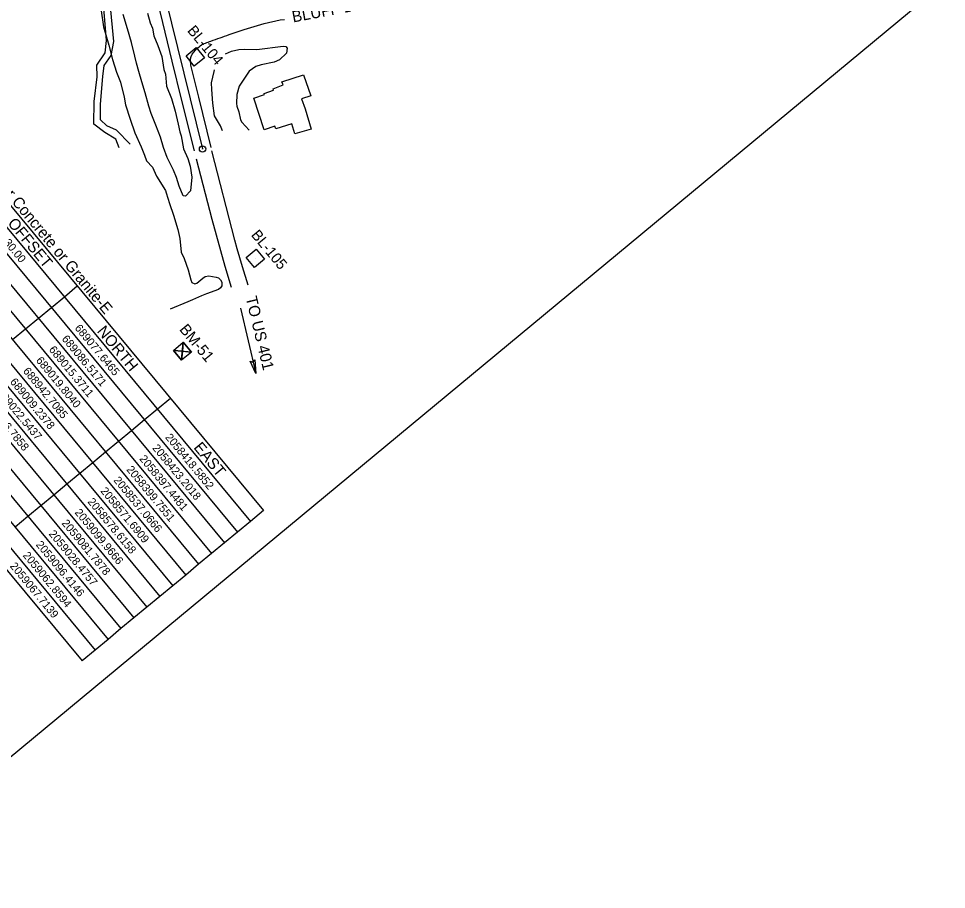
# Model space of a CAD drawing. Extents: x 2057130 to 2060012, y 687175 to 689912.
# Drawn here: x 2058941 to 2059967, y 687175 to 688138 of the extents above; entities that cross this region are included whole.
import ezdxf

# ---------------------------------------------------------------- set-up
doc = ezdxf.new("R2010")
doc.units = 0
for name, color, linetype in [('CTL Bench Mark CELL', 7, 'Continuous'), ('CTL Bench Mark Text', 7, 'Continuous'), ('CTL Sheet Border CELL', 7, 'Continuous'), ('CTL Sheet Notes CELL', 7, 'Continuous'), ('CTL Sheet Table Cell', 7, 'Continuous'), ('CTL Sheet Text', 7, 'Continuous'), ('CTL Supplemental Horizontal and Vertical CELL', 7, 'Continuous'), ('CTL Supplemental Horizontal and Vertical Text', 7, 'Continuous'), ('Default', 7, 'Continuous'), ('Exist Roads EOP', 7, 'Continuous'), ('Exist Roads Soil', 7, 'Continuous'), ('Old_Level_11', 7, 'Continuous'), ('Old_Level_3', 7, 'Continuous'), ('Old_Level_8', 7, 'Continuous'), ('Old_Level_9', 7, 'Continuous'), ('Prop Horizontal Alignment', 7, 'Continuous'), ('Prop Terminator CELL', 7, 'Continuous')]:
    doc.layers.add(name, color=color, linetype=linetype)

msp = doc.modelspace()

# ---------------------------------------------------------------- linework, layer by layer
at = {"layer": 'CTL Bench Mark CELL'}
msp.add_line((2059122.2, 687770), (2059122.2, 687770), dxfattribs=at)
msp.add_lwpolyline([(2059123.1, 687779.9), (2059132.1, 687769.1), (2059121.3, 687760.1), (2059112.3, 687770.9)], close=True, dxfattribs=at)
for points in [[(2059132.1, 687769.1), (2059112.3, 687770.9), (2059122.2, 687770), (2059121.3, 687760.1), (2059123.1, 687779.9)], [(2059122.2, 687770), (2059132.1, 687769.1), (2059123.1, 687779.9), (2059122.2, 687770)], [(2059122.2, 687770), (2059112.3, 687770.9), (2059121.3, 687760.1), (2059122.2, 687770)]]:
    msp.add_lwpolyline(points, dxfattribs=at)
at = {"layer": 'CTL Sheet Border CELL'}
msp.add_lwpolyline([(2059967.3, 688179.9), (2058531.1, 689911.9), (2057318.7, 688906.6), (2058754.9, 687174.6)], close=True, dxfattribs=at)
at = {"layer": 'CTL Sheet Table Cell'}
for p, q in [((2058768.5, 688128.2), (2059211.8, 687593.7)), ((2058754.2, 688116.4), (2059197.5, 687581.8)), ((2058739.9, 688104.5), (2059183.2, 687569.9)), ((2058725.6, 688092.6), (2059168.8, 687558)), ((2058711.2, 688080.7), (2059154.5, 687546.2)), ((2058696.9, 688068.9), (2059140.2, 687534.3)), ((2058682.6, 688057), (2059125.9, 687522.4)), ((2058668.3, 688045.1), (2059111.6, 687510.6)), ((2058654, 688033.2), (2059097.3, 687498.7)), ((2058639.6, 688021.4), (2059082.9, 687486.8)), ((2058625.3, 688009.5), (2059068.6, 687474.9)), ((2058611, 687997.6), (2059054.3, 687463.1)), ((2058596.7, 687985.7), (2059040, 687451.2)), ((2058582.4, 687973.9), (2059025.7, 687439.3)), ((2058568.1, 687962), (2059011.3, 687427.4)), ((2059006, 687841.9), (2058991.7, 687830)), ((2058991.7, 687830), (2058977.4, 687818.1)), ((2058977.4, 687818.1), (2058963, 687806.2)), ((2058963, 687806.2), (2058948.7, 687794.4)), ((2058948.7, 687794.4), (2058934.4, 687782.5)), ((2059108.9, 687717.8), (2059094.6, 687705.9)), ((2059094.6, 687705.9), (2059080.3, 687694)), ((2059080.3, 687694), (2059065.9, 687682.1)), ((2059065.9, 687682.1), (2059051.6, 687670.3)), ((2059051.6, 687670.3), (2059037.3, 687658.4)), ((2059037.3, 687658.4), (2059023, 687646.5)), ((2059023, 687646.5), (2059008.7, 687634.6)), ((2059008.7, 687634.6), (2058994.3, 687622.8)), ((2058994.3, 687622.8), (2058980, 687610.9)), ((2058980, 687610.9), (2058965.7, 687599)), ((2058965.7, 687599), (2058951.4, 687587.2)), ((2059211.8, 687593.7), (2059197.5, 687581.8)), ((2058951.4, 687587.2), (2058937.1, 687575.3)), ((2059197.5, 687581.8), (2059183.2, 687569.9)), ((2059183.2, 687569.9), (2059168.8, 687558)), ((2059168.8, 687558), (2059154.5, 687546.2)), ((2059154.5, 687546.2), (2059140.2, 687534.3)), ((2059140.2, 687534.3), (2059125.9, 687522.4)), ((2059125.9, 687522.4), (2059111.6, 687510.6)), ((2059111.6, 687510.6), (2059097.3, 687498.7)), ((2059097.3, 687498.7), (2059082.9, 687486.8)), ((2059082.9, 687486.8), (2059068.6, 687474.9)), ((2059068.6, 687474.9), (2059054.3, 687463.1)), ((2059054.3, 687463.1), (2059040, 687451.2)), ((2059040, 687451.2), (2059025.7, 687439.3)), ((2059025.7, 687439.3), (2059011.3, 687427.4))]:
    msp.add_line(p, q, dxfattribs=at)
at = {"layer": 'CTL Supplemental Horizontal and Vertical CELL'}
for p, q in [((2059136.4, 688095.8), (2059136.4, 688095.8)), ((2059202.8, 687872.9), (2059202.8, 687872.9))]:
    msp.add_line(p, q, dxfattribs=at)
for points in [[(2059137.4, 688105.9), (2059146.6, 688094.8), (2059135.4, 688085.5), (2059126.2, 688096.7)], [(2059203.8, 687883), (2059213, 687871.9), (2059201.8, 687862.6), (2059192.6, 687873.8)]]:
    msp.add_lwpolyline(points, close=True, dxfattribs=at)
at = {"layer": 'Default'}
msp.add_line((2059186.5, 687817.5), (2059203.5, 687745.4), dxfattribs=at)
at = {"layer": 'Exist Roads EOP'}
for points in [[(2059055, 688316.7), (2059066, 688272.7), (2059077.4, 688227.6), (2059088.7, 688180.9), (2059100.3, 688133.6), (2059110.5, 688090.8), (2059121.2, 688047.3), (2059135.1, 687991.8)], [(2059173.8, 688120.4), (2059190.7, 688126), (2059212.5, 688132.6), (2059230.5, 688136.7), (2059235.2, 688137.1)], [(2059173.8, 688120.4), (2059190.7, 688126), (2059212.5, 688132.6), (2059230.5, 688136.7), (2059235.2, 688137.1)], [(2059153.9, 687995.3), (2059140.4, 688051.1), (2059131.7, 688086.5)], [(2059153.9, 687995.3), (2059140.4, 688051.1), (2059131.7, 688086.5)]]:
    msp.add_lwpolyline(points, dxfattribs=at)
msp.add_spline([(2059131.7, 688086.5), (2059131.2, 688093.5), (2059136.7, 688103.2), (2059142, 688108), (2059153.8, 688113.2), (2059173.8, 688120.4)], degree=3, dxfattribs=at)
msp.add_spline([(2059131.7, 688086.5), (2059131.2, 688093.5), (2059136.7, 688103.2), (2059142, 688108), (2059153.8, 688113.2), (2059173.8, 688120.4)], degree=3, dxfattribs=at)
at = {"layer": 'Exist Roads Soil'}
for points in [[(2059052.2, 687995.2), (2059048.6, 688004.7), (2059036.6, 688012), (2059024.3, 688021.4), (2059024.5, 688046.5), (2059027.8, 688073.7), (2059027.7, 688086.5), (2059036.8, 688100.1), (2059038.4, 688113.9), (2059035.1, 688154), (2059029.1, 688197.2), (2059028.3, 688232.7), (2059023.4, 688269.4), (2059017.9, 688292.4), (2059014.2, 688311.6)], [(2059064.5, 687999), (2059049.5, 688014.7), (2059038.8, 688019.5), (2059031.5, 688025.9), (2059031.5, 688043.3), (2059034.2, 688073.9), (2059035.5, 688086), (2059043.3, 688097.2), (2059046.4, 688112.6), (2059042.5, 688155.2), (2059036.9, 688199.3), (2059035.9, 688233.3), (2059030.1, 688272.5), (2059024.3, 688296.5), (2059020.7, 688316)]]:
    msp.add_lwpolyline(points, dxfattribs=at)
at = {"layer": 'Old_Level_11'}
for points in [[(2059032.2, 688146.5), (2059035.1, 688129), (2059040.9, 688108.6), (2059044.8, 688092.7), (2059049.3, 688078.7), (2059053.7, 688067.7), (2059057.8, 688051.3), (2059059.2, 688042.7), (2059064.5, 688026.6), (2059069.6, 688011.5), (2059076.6, 687996.3), (2059080.3, 687986.9), (2059082.5, 687980.8), (2059089, 687973.5), (2059093.6, 687963.9), (2059103.5, 687948), (2059104.3, 687945.4), (2059107.8, 687933.3), (2059112.5, 687920.4), (2059117, 687904.6), (2059119.3, 687894.7), (2059120.9, 687879.5), (2059124.1, 687872.7), (2059128.5, 687860), (2059131.5, 687848.9), (2059132.7, 687846), (2059135.8, 687844.5), (2059138.2, 687845.5), (2059144.8, 687851), (2059147.4, 687852.6), (2059151.3, 687853.5), (2059159.4, 687852.1), (2059162, 687851.2), (2059164.2, 687849.1), (2059165.8, 687846.5), (2059165.7, 687842.5), (2059164.4, 687840.3), (2059162, 687838.5), (2059148.9, 687833.4), (2059143.5, 687831.4), (2059133.4, 687826.9), (2059128.2, 687824.7), (2059108.6, 687816.7)], [(2059083.5, 688143.9), (2059086.4, 688133.2), (2059089.3, 688127.6), (2059090.8, 688119.1), (2059094.9, 688108.1), (2059099.4, 688096.1), (2059101.7, 688081.9), (2059103.4, 688076.4), (2059104.8, 688063.2), (2059110.1, 688049.7), (2059114.1, 688035.6), (2059117.4, 688021.3), (2059119.3, 688012.8), (2059120.8, 688008.5), (2059123.3, 687994.1), (2059128.2, 687983.1), (2059130.8, 687974.9)], [(2059130.8, 687974.9), (2059132.8, 687962.5), (2059131.3, 687947.4), (2059125.6, 687941.6), (2059122.9, 687942.1), (2059118.8, 687952.5), (2059115.6, 687962.3), (2059112.5, 687970.5), (2059105.5, 687984.2), (2059101.3, 687995.4), (2059097.9, 688006.8), (2059092.7, 688020.2), (2059087.7, 688033.1), (2059085, 688041), (2059081.1, 688055.8), (2059077.3, 688068.1), (2059074, 688079.6), (2059071.4, 688088.9), (2059069.7, 688096.6), (2059066.1, 688111.6), (2059061.4, 688126.9), (2059056.8, 688142.6)], [(2059170, 688099.2), (2059176.7, 688102), (2059184.8, 688103.8), (2059191, 688104.2), (2059204.7, 688103.9), (2059233.6, 688107.6), (2059236.5, 688107.1), (2059238.2, 688105.2), (2059237.2, 688099.9), (2059229.6, 688092.5), (2059223.9, 688089.8), (2059209.2, 688087), (2059203.6, 688085.1), (2059196, 688079.9), (2059185.1, 688063.2), (2059182.4, 688053.9), (2059182.1, 688044), (2059182.5, 688041), (2059184.7, 688035), (2059186.6, 688025.9), (2059188, 688023.5), (2059195.9, 688014.5)], [(2059166.5, 688013.7), (2059164.2, 688019.4), (2059157.7, 688030.6), (2059155.8, 688044.6), (2059154.8, 688059.5), (2059154.5, 688067), (2059157.2, 688079.5), (2059157.7, 688081.3)]]:
    msp.add_lwpolyline(points, dxfattribs=at)
at = {"layer": 'Old_Level_3'}
for points in [[(2059195, 687843.2), (2059188.7, 687863.3), (2059182.8, 687883.5), (2059180.2, 687892.9), (2059154.6, 687991.7)], [(2059137.6, 687983), (2059154.6, 687916), (2059169, 687864.2), (2059176, 687840.8)]]:
    msp.add_lwpolyline(points, dxfattribs=at)
at = {"layer": 'Old_Level_8'}
msp.add_lwpolyline([(2059243.1, 688021.6), (2059225.6, 688016), (2059224.4, 688019), (2059212.7, 688015), (2059201.1, 688050.1), (2059213, 688054), (2059212.6, 688055.1), (2059222.9, 688059), (2059222.7, 688060.5), (2059233.5, 688064.9), (2059232.3, 688068.1), (2059256.2, 688076), (2059264.2, 688052.5), (2059254.1, 688049.2), (2059257.9, 688038.1), (2059264.5, 688015.9), (2059246.4, 688010.5), (2059243.1, 688021.6)], dxfattribs=at)
at = {"layer": 'Prop Horizontal Alignment'}
msp.add_line((2059062.5, 688326.2), (2059144.5, 687993.8), dxfattribs=at)
for radius in [3.55, 0.114]:
    msp.add_circle((2059144.5, 687993.8), radius, dxfattribs=at)
at = {"layer": 'Prop Terminator CELL'}
msp.add_lwpolyline([(2059202.2, 687760.4), (2059203.5, 687745.4), (2059197.2, 687759.1), (2059200.2, 687758)], close=True, dxfattribs=at)

# ---------------------------------------------------------------- texts
at = {"layer": 'CTL Bench Mark Text'}
msp.add_text('BM-51', height=12.21, rotation=309.6672, dxfattribs=at).set_placement((2059118.2, 687793.9))
at = {"layer": 'CTL Sheet Notes CELL'}
for s, height, p in [('ROW Marker Concrete or Granite-E', 12.401, (2058868.2, 688012.9)), ('OFFSET', 12.4, (2058928.3, 687911.3)), ('NORTH', 12.4, (2059027.2, 687792)), ('EAST', 12.4, (2059134, 687663.2))]:
    msp.add_text(s, height=height, rotation=309.6672, dxfattribs=at).set_placement(p)
at = {"layer": 'CTL Sheet Text'}
for s, height, p in [('-30.00', 8.86, (2058921.7, 687892.9)), ('689077.6465', 8.858, (2059002.6, 687795.3)), ('689086.5171', 8.858, (2058988.3, 687783.4)), ('689015.3711', 8.858, (2058974, 687771.5)), ('689019.8040', 8.858, (2058959.7, 687759.6)), ('688942.7085', 8.858, (2058945.4, 687747.8)), ('689009.2378', 8.858, (2058931, 687735.9)), ('689022.5437', 8.858, (2058916.7, 687724)), ('688396.7858', 8.858, (2058902.4, 687712.1)), ('2058418.5852', 8.858, (2059102.7, 687674.5)), ('2058423.2018', 8.858, (2059088.4, 687662.7)), ('2058397.4481', 8.858, (2059074.1, 687650.8)), ('2058399.7551', 8.858, (2059059.8, 687638.9)), ('2058537.0666', 8.858, (2059045.5, 687627)), ('2058571.6909', 8.858, (2059031.1, 687615.2)), ('2058578.6158', 8.858, (2059016.8, 687603.3)), ('2059099.9666', 8.858, (2059002.5, 687591.4)), ('2059081.7878', 8.858, (2058988.2, 687579.5)), ('2059028.4757', 8.858, (2058973.9, 687567.7)), ('2059096.4146', 8.858, (2058959.6, 687555.8)), ('2059062.8594', 8.858, (2058945.2, 687543.9)), ('2059067.7139', 8.858, (2058930.9, 687532.1))]:
    msp.add_text(s, height=height, rotation=309.6672, dxfattribs=at).set_placement(p)
at = {"layer": 'CTL Supplemental Horizontal and Vertical Text'}
for s, p in [('BL-104', (2059127, 688124.5)), ('BL-105', (2059197.6, 687898.4))]:
    msp.add_text(s, height=11.79, rotation=309.6672, dxfattribs=at).set_placement(p)
at = {"layer": 'Default'}
msp.add_text('BLUFF DR.', height=12.5, rotation=10.692, dxfattribs=at).set_placement((2059244.7, 688133.7))
at = {"layer": 'Old_Level_9'}
msp.add_text('TO US 401', height=12.5, rotation=283.5418, dxfattribs=at).set_placement((2059192.1, 687829.3))

doc.saveas('drawing.dxf')
